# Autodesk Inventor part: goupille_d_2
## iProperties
Shininess: 64.0
Length Units: 11269
Angle Units: 11279
Time Units: 11290
Mass Units: 11283
Length Display Precision: 3
Angle Display Precision: 2
Compacted: True
Part Number: goupille_d_2
Document SubType Name: Modeling
Created: 2004-05
Material: Par défaut
Designer: David
Density: 0.0
Volumn: 0.0
Area: 0.0
PropertySet Name: Model Information
Control State: 0
Master: False
Checked Out: False
Author: David
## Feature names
1. Extrusion1
2. Chanfrein1 [Chamfer]
